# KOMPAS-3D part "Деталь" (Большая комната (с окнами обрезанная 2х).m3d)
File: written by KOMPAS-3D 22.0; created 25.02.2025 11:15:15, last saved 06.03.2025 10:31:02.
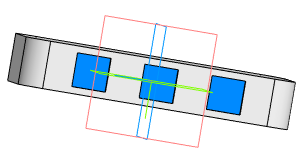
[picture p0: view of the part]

Document properties: Автор: Пользователь Windows; Полное имя файла: C:\Users\Student\Documents\Картошечка\База Сабнатика\Большая комната\Большая комната (с окнами обрезанная 2х).m3d

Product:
- Part/product: Деталь
    Масса: 1.350426

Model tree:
1. Эскиз:1
2. Элемент выдавливания:1
     Расстояние 1 = 35
3. Скругление:2  (with: Элемент выдавливания:1)
     Радиус = 10
4. Скругление:1  (with: Элемент выдавливания:1)
     Радиус = 7
5. Эскиз:2  (with: Элемент выдавливания:1, Скругление:1)
6. Элемент выдавливания:2
     Расстояние 2 = 2
7. Зеркальный массив:1
8. Экземпляр ( 1 )
9. Экземпляр ( 2 )  (with: Элемент выдавливания:2)
10. Эскиз:3  (with: Элемент выдавливания:1)
11. Элемент выдавливания:3
     Расстояние 2 = 7
12. Эскиз:4  (with: Элемент выдавливания:1)
13. Элемент выдавливания:4
     Расстояние 2 = 7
